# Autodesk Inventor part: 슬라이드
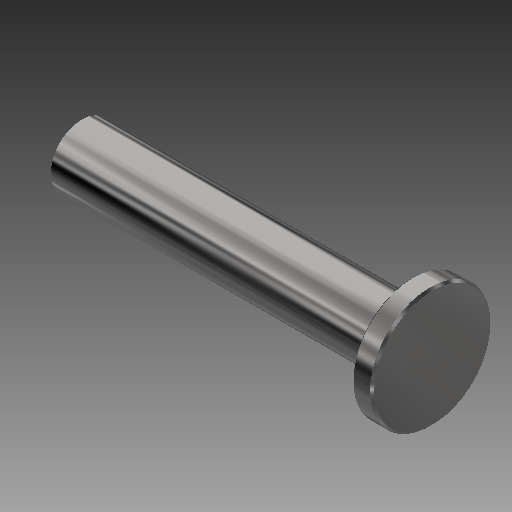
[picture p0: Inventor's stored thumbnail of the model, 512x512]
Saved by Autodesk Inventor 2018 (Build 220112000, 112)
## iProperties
Created: 2015-10
Part Number: 슬라이드
Document SubType Name: Modeling
Designer: mdu
Density: 1 g/cm^3
Material: 강철, 연강
Appearance: 강철 - 광택
Author: mdu
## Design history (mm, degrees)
sketch "스케치1"
  geometry: L1 (-75, 162)-(-75, 58) reference; L2 (-148, 110)-(22, 110); L3 (-148, 110)-(-148, 125); L4 (-148, 125)-(12, 125); L5 (12, 125)-(12, 139); L6 (12, 139)-(22, 139); L7 (22, 139)-(22, 110); 2 further points
  constraints: 12 end point, 3 parallel, 3 perpendicular, 1 midpoint, 1 point on line
  dimensions: "d0" = 58 diameter of L6 L2; "d1" = 30 diameter of L4 L2; "d2" = 10 distance of L5.end L6.end; "d3" = 170 distance of L2.start L2.end; "d4" = 73 distance between parallel lines of L3 L1
revolve "회전1" sketch "스케치1" stored, may be unused: angle "d5" = 90 deg
hole "구멍1" diameter "d11" = 13.376; stored, may be unused: countersink angle "d15" = 90 deg, drill point angle "d17" = 118 deg; dims "d9" = 10, "d10" = 10, "d12" = 22, "d13" = 4, "d14" = 2, "d16" = 25
chamfer "모따기1" distance "d6" = 1; stored, may be unused: second distance "d7" = 2, angle "d8" = 45 deg
node "솔리드1"
node "참조1"
